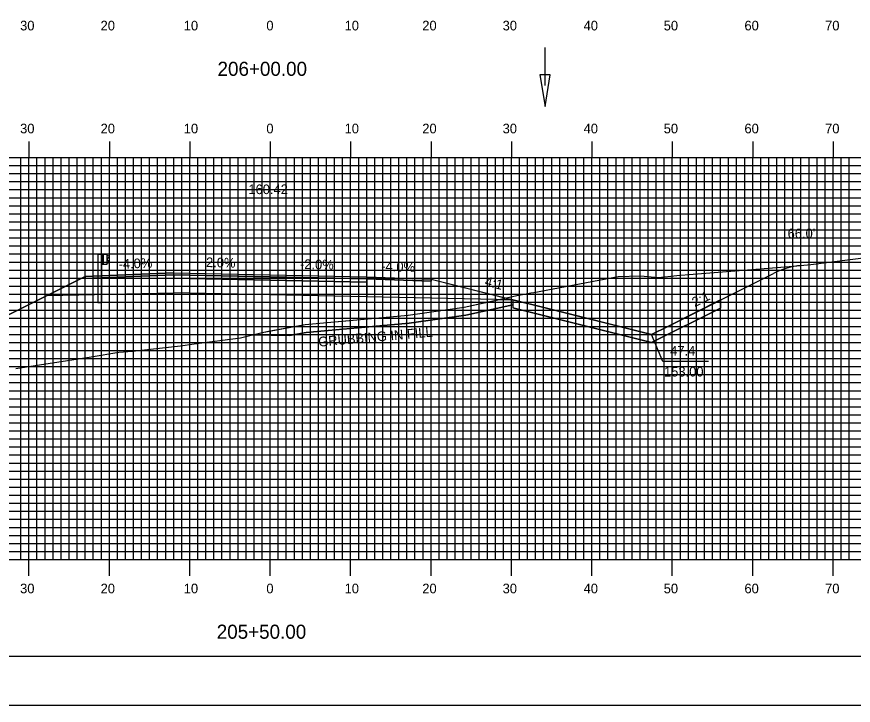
# Model space of a CAD drawing. Extents: x 1793272 to 1793615, y 442591 to 442811.
# Drawn here: x 1793406.3 to 1793510.3, y 442590.5 to 442676.2 of the extents above; entities that cross this region are included whole.
import ezdxf

# ---------------------------------------------------------------- set-up
doc = ezdxf.new("R2010")
doc.units = 0
for name, color, linetype in [('ANNOTATION', 7, 'Continuous'), ('BORDER', 7, 'Continuous'), ('D_Drainage_Ditch_Line', 7, 'Continuous'), ('D_Guardrail_Beam_Lt', 7, 'Continuous'), ('D_Roadway_Centerline', 7, 'Continuous'), ('D_Roadway_Centerline_Text', 7, 'Continuous'), ('D_Roadway_Edge_Shoulder', 7, 'Continuous'), ('D_Roadway_Edge_TW', 7, 'Continuous'), ('D_Roadway_FinishedGrade', 7, 'Continuous'), ('D_Roadway_Pavement', 7, 'Continuous'), ('D_Roadway_SlopeLines', 7, 'Continuous'), ('D_Roadway_SubGrade', 7, 'Continuous'), ('D_Text_Standard', 7, 'Continuous'), ('GRUBBING IN FILL', 7, 'Continuous'), ('H_V ANNOTATION', 7, 'Continuous'), ('MAJOR', 7, 'Continuous'), ('MINOR', 7, 'Continuous'), ('PATTERNING', 7, 'Continuous'), ('PLOT BOUNDARY', 7, 'Continuous'), ('S_Roadway_Centerline', 7, 'Continuous')]:
    doc.layers.add(name, color=color, linetype=linetype)

msp = doc.modelspace()

# ---------------------------------------------------------------- linework, layer by layer
at = {"layer": 'ANNOTATION'}
msp.add_lwpolyline([(1793492.31, 442633.3), (1793486.62, 442633.3), (1793485.23, 442636.67)], dxfattribs=at)
at = {"layer": 'BORDER'}
msp.add_lwpolyline([(1793288.2, 442596.67), (1793608.2, 442596.67), (1793608.2, 442806.67), (1793288.2, 442806.67)], close=True, dxfattribs=at)
at = {"layer": 'D_Drainage_Ditch_Line'}
msp.add_line((1793471.98, 442667.63), (1793471.97, 442672.33), dxfattribs=at)
msp.add_lwpolyline([(1793472.63, 442668.94), (1793471.32, 442668.94), (1793471.98, 442665)], close=True, dxfattribs=at)
at = {"layer": 'D_Guardrail_Beam_Lt'}
for p, q in [((1793416.37, 442646.59), (1793416.37, 442640.59)), ((1793416.84, 442646.59), (1793416.37, 442646.59)), ((1793417.53, 442646.59), (1793416.84, 442646.59)), ((1793416.84, 442646.59), (1793416.84, 442645.42)), ((1793416.9, 442646.59), (1793416.9, 442645.42)), ((1793417.01, 442646.59), (1793417.01, 442645.42)), ((1793417.53, 442645.42), (1793417.53, 442646.59)), ((1793417.53, 442646.5), (1793417.6, 442646.49)), ((1793417.53, 442646.04), (1793417.53, 442645.97)), ((1793417.76, 442646.24), (1793417.57, 442646.1)), ((1793417.57, 442645.9), (1793417.76, 442645.77)), ((1793417.62, 442646.48), (1793417.76, 442646.38)), ((1793416.84, 442645.42), (1793417.53, 442645.42)), ((1793416.86, 442640.59), (1793416.86, 442645.42)), ((1793417.6, 442645.52), (1793417.53, 442645.5)), ((1793417.76, 442645.62), (1793417.62, 442645.52)), ((1793416.86, 442640.59), (1793416.37, 442640.59))]:
    msp.add_line(p, q, dxfattribs=at)
for centre, major_axis, start_param, end_param in [((1793417.61, 442646.04), (-0.0789, 0), 5.323254, 6.283185), ((1793417.61, 442645.97), (-0.0789, 0), 6.283185, 7.243116), ((1793417.6, 442646.45), (0.0417, 0), 0.959931, 1.376053), ((1793417.71, 442646.31), (0.0877, 0), 5.323254, 7.243116), ((1793417.6, 442645.56), (0.0417, 0), 4.907132, 5.323254), ((1793417.71, 442645.7), (0.0877, 0), 5.323254, 7.243116)]:
    msp.add_ellipse(centre, major_axis=major_axis, ratio=0.995501, start_param=start_param, end_param=end_param, dxfattribs=at)
at = {"layer": 'D_Roadway_Centerline'}
msp.add_lwpolyline([(1793384.25, 442628.61), (1793410.05, 442641.51), (1793414.8, 442643.88), (1793417.8, 442644), (1793425.8, 442644.32), (1793437.8, 442644.08), (1793449.8, 442643.84), (1793457.8, 442643.52), (1793467.97, 442640.98), (1793471.97, 442639.98)], dxfattribs=at)
at = {"layer": 'D_Roadway_Edge_Shoulder'}
for points in [[(1793425.8, 442644.32), (1793417.8, 442644), (1793417.8, 442644), (1793414.8, 442643.88), (1793414.8, 442643.63), (1793425.8, 442644.07)], [(1793449.8, 442643.84), (1793457.8, 442643.52), (1793457.8, 442643.27), (1793449.8, 442643.59)]]:
    msp.add_lwpolyline(points, close=True, dxfattribs=at)
at = {"layer": 'D_Roadway_Edge_TW'}
msp.add_lwpolyline([(1793425.8, 442644.07), (1793425.8, 442644.32), (1793437.8, 442644.08), (1793449.8, 442643.84), (1793449.8, 442643.59), (1793437.8, 442643.83)], close=True, dxfattribs=at)
at = {"layer": 'D_Roadway_FinishedGrade'}
for p, q in [((1793457.8, 442643.52), (1793485.23, 442636.67)), ((1793467.97, 442640.98), (1793467.97, 442639.98))]:
    msp.add_line(p, q, dxfattribs=at)
for points in [[(1793485.23, 442636.67), (1793487.23, 442637.67), (1793500.39, 442644.25)], [(1793493.8, 442640.95), (1793493.8, 442639.95), (1793485.23, 442635.67)], [(1793485.23, 442635.67), (1793467.97, 442639.98)]]:
    msp.add_lwpolyline(points, dxfattribs=at)
msp.add_arc((1793504.86, 442635.3), 10, 96.007, 116.5651, dxfattribs=at)
at = {"layer": 'D_Roadway_Pavement'}
msp.add_lwpolyline([(1793425.8, 442643.66), (1793425.8, 442644.07), (1793437.8, 442643.83), (1793449.8, 442643.59), (1793449.8, 442643.18), (1793437.8, 442643.42)], close=True, dxfattribs=at)
for points in [[(1793425.8, 442644.07), (1793425.8, 442643.66)], [(1793449.8, 442643.59), (1793449.8, 442643.18)]]:
    msp.add_lwpolyline(points, dxfattribs=at)
at = {"layer": 'D_Roadway_SlopeLines'}
for points in [[(1793414.8, 442643.88), (1793384.25, 442628.61)], [(1793457.8, 442643.52), (1793471.97, 442639.98)]]:
    msp.add_lwpolyline(points, dxfattribs=at)
at = {"layer": 'D_Roadway_SubGrade'}
for points in [[(1793425.8, 442643.66), (1793425.8, 442644.07), (1793414.8, 442643.63), (1793414.8, 442643.88), (1793410.05, 442641.51), (1793425.8, 442641.82)], [(1793425.8, 442641.82), (1793425.8, 442644.07), (1793425.8, 442643.66), (1793437.8, 442643.42), (1793449.8, 442643.18), (1793449.8, 442643.59), (1793449.8, 442641.34), (1793437.8, 442641.58)], [(1793449.8, 442643.18), (1793449.8, 442643.59), (1793457.8, 442643.27), (1793457.8, 442643.52), (1793467.97, 442640.98), (1793449.8, 442641.34)]]:
    msp.add_lwpolyline(points, close=True, dxfattribs=at)
at = {"layer": 'GRUBBING IN FILL'}
for points in [[(1793437.8, 442636.58), (1793437.8, 442637.11), (1793442.15, 442637.91), (1793448.55, 442638.49), (1793454.95, 442639.07), (1793458.44, 442639.56), (1793461.93, 442640.04), (1793466.31, 442641.01), (1793467.97, 442640.98), (1793467.97, 442640.36), (1793462.11, 442639.06), (1793458.59, 442638.57), (1793455.07, 442638.08), (1793448.68, 442637.5), (1793442.28, 442636.92), (1793440.2, 442636.53)], [(1793437.8, 442636.58), (1793437.8, 442637.11), (1793442.15, 442637.91), (1793448.55, 442638.49), (1793454.95, 442639.07), (1793458.44, 442639.56), (1793461.93, 442640.04), (1793466.31, 442641.01), (1793467.97, 442640.98), (1793467.97, 442640.36), (1793462.11, 442639.06), (1793458.59, 442638.57), (1793455.07, 442638.08), (1793448.68, 442637.5), (1793442.28, 442636.92), (1793440.2, 442636.53)], [(1793435.62, 442636.63), (1793436.78, 442636.92), (1793437.8, 442637.11), (1793437.8, 442636.58)], [(1793435.62, 442636.63), (1793436.78, 442636.92), (1793437.8, 442637.11), (1793437.8, 442636.58)]]:
    msp.add_lwpolyline(points, close=True, dxfattribs=at)
for points in [[(1793440.2, 442636.53), (1793442.28, 442636.92), (1793455.07, 442638.08), (1793462.11, 442639.06), (1793467.97, 442640.36)], [(1793440.2, 442636.53), (1793442.28, 442636.92), (1793455.07, 442638.08), (1793462.11, 442639.06), (1793467.97, 442640.36)], [(1793435.62, 442636.63), (1793440.2, 442636.53)], [(1793435.62, 442636.63), (1793440.2, 442636.53)]]:
    msp.add_lwpolyline(points, dxfattribs=at)
at = {"layer": 'MAJOR'}
for p, q in [((1793407.8, 442660.67), (1793407.8, 442658.67)), ((1793417.8, 442660.67), (1793417.8, 442658.67)), ((1793427.8, 442660.67), (1793427.8, 442658.67)), ((1793437.8, 442660.67), (1793437.8, 442658.67)), ((1793447.8, 442660.67), (1793447.8, 442658.67)), ((1793457.8, 442660.67), (1793457.8, 442658.67)), ((1793467.8, 442660.67), (1793467.8, 442658.67)), ((1793477.8, 442660.67), (1793477.8, 442658.67)), ((1793487.8, 442660.67), (1793487.8, 442658.67)), ((1793497.8, 442660.67), (1793497.8, 442658.67)), ((1793507.8, 442660.67), (1793507.8, 442658.67)), ((1793297.8, 442658.67), (1793577.8, 442658.67)), ((1793297.8, 442658.67), (1793577.8, 442658.67)), ((1793407.8, 442608.67), (1793407.8, 442658.67)), ((1793417.8, 442608.67), (1793417.8, 442658.67)), ((1793427.8, 442608.67), (1793427.8, 442658.67)), ((1793437.8, 442608.67), (1793437.8, 442658.67)), ((1793447.8, 442608.67), (1793447.8, 442658.67)), ((1793457.8, 442608.67), (1793457.8, 442658.67)), ((1793467.8, 442608.67), (1793467.8, 442658.67)), ((1793477.8, 442608.67), (1793477.8, 442658.67)), ((1793487.8, 442608.67), (1793487.8, 442658.67)), ((1793497.8, 442608.67), (1793497.8, 442658.67)), ((1793507.8, 442608.67), (1793507.8, 442658.67)), ((1793297.8, 442653.67), (1793577.8, 442653.67)), ((1793297.8, 442648.67), (1793577.8, 442648.67)), ((1793297.8, 442643.67), (1793577.8, 442643.67)), ((1793297.8, 442638.67), (1793577.8, 442638.67)), ((1793297.8, 442633.67), (1793577.8, 442633.67)), ((1793297.8, 442628.67), (1793577.8, 442628.67)), ((1793297.8, 442623.67), (1793577.8, 442623.67)), ((1793297.8, 442618.67), (1793577.8, 442618.67)), ((1793297.8, 442613.67), (1793577.8, 442613.67)), ((1793297.8, 442608.67), (1793577.8, 442608.67)), ((1793297.8, 442608.67), (1793577.8, 442608.67)), ((1793407.8, 442606.66), (1793407.8, 442608.67)), ((1793417.8, 442606.66), (1793417.8, 442608.67)), ((1793427.8, 442606.66), (1793427.8, 442608.67)), ((1793437.8, 442606.66), (1793437.8, 442608.67)), ((1793447.8, 442606.66), (1793447.8, 442608.67)), ((1793457.8, 442606.66), (1793457.8, 442608.67)), ((1793467.8, 442606.66), (1793467.8, 442608.67)), ((1793477.8, 442606.66), (1793477.8, 442608.67)), ((1793487.8, 442606.66), (1793487.8, 442608.67)), ((1793497.8, 442606.66), (1793497.8, 442608.67)), ((1793507.8, 442606.66), (1793507.8, 442608.67))]:
    msp.add_line(p, q, dxfattribs=at)
at = {"layer": 'MINOR'}
for p, q in [((1793406.8, 442608.67), (1793406.8, 442658.67)), ((1793408.8, 442608.67), (1793408.8, 442658.67)), ((1793409.8, 442608.67), (1793409.8, 442658.67)), ((1793410.8, 442608.67), (1793410.8, 442658.67)), ((1793411.8, 442608.67), (1793411.8, 442658.67)), ((1793412.8, 442608.67), (1793412.8, 442658.67)), ((1793413.8, 442608.67), (1793413.8, 442658.67)), ((1793414.8, 442608.67), (1793414.8, 442658.67)), ((1793415.8, 442608.67), (1793415.8, 442658.67)), ((1793416.8, 442608.67), (1793416.8, 442658.67)), ((1793418.8, 442608.67), (1793418.8, 442658.67)), ((1793419.8, 442608.67), (1793419.8, 442658.67)), ((1793420.8, 442608.67), (1793420.8, 442658.67)), ((1793421.8, 442608.67), (1793421.8, 442658.67)), ((1793422.8, 442608.67), (1793422.8, 442658.67)), ((1793423.8, 442608.67), (1793423.8, 442658.67)), ((1793424.8, 442608.67), (1793424.8, 442658.67)), ((1793425.8, 442608.67), (1793425.8, 442658.67)), ((1793426.8, 442608.67), (1793426.8, 442658.67)), ((1793428.8, 442608.67), (1793428.8, 442658.67)), ((1793429.8, 442608.67), (1793429.8, 442658.67)), ((1793430.8, 442608.67), (1793430.8, 442658.67)), ((1793431.8, 442608.67), (1793431.8, 442658.67)), ((1793432.8, 442608.67), (1793432.8, 442658.67)), ((1793433.8, 442608.67), (1793433.8, 442658.67)), ((1793434.8, 442608.67), (1793434.8, 442658.67)), ((1793435.8, 442608.67), (1793435.8, 442658.67)), ((1793436.8, 442608.67), (1793436.8, 442658.67)), ((1793438.8, 442608.67), (1793438.8, 442658.67)), ((1793439.8, 442608.67), (1793439.8, 442658.67)), ((1793440.8, 442608.67), (1793440.8, 442658.67)), ((1793441.8, 442608.67), (1793441.8, 442658.67)), ((1793442.8, 442608.67), (1793442.8, 442658.67)), ((1793443.8, 442608.67), (1793443.8, 442658.67)), ((1793444.8, 442608.67), (1793444.8, 442658.67)), ((1793445.8, 442608.67), (1793445.8, 442658.67)), ((1793446.8, 442608.67), (1793446.8, 442658.67)), ((1793448.8, 442608.67), (1793448.8, 442658.67)), ((1793449.8, 442608.67), (1793449.8, 442658.67)), ((1793450.8, 442608.67), (1793450.8, 442658.67)), ((1793451.8, 442608.67), (1793451.8, 442658.67)), ((1793452.8, 442608.67), (1793452.8, 442658.67)), ((1793453.8, 442608.67), (1793453.8, 442658.67)), ((1793454.8, 442608.67), (1793454.8, 442658.67)), ((1793455.8, 442608.67), (1793455.8, 442658.67)), ((1793456.8, 442608.67), (1793456.8, 442658.67)), ((1793458.8, 442608.67), (1793458.8, 442658.67)), ((1793459.8, 442608.67), (1793459.8, 442658.67)), ((1793460.8, 442608.67), (1793460.8, 442658.67)), ((1793461.8, 442608.67), (1793461.8, 442658.67)), ((1793462.8, 442608.67), (1793462.8, 442658.67)), ((1793463.8, 442608.67), (1793463.8, 442658.67)), ((1793464.8, 442608.67), (1793464.8, 442658.67)), ((1793465.8, 442608.67), (1793465.8, 442658.67)), ((1793466.8, 442608.67), (1793466.8, 442658.67)), ((1793468.8, 442608.67), (1793468.8, 442658.67)), ((1793469.8, 442608.67), (1793469.8, 442658.67)), ((1793470.8, 442608.67), (1793470.8, 442658.67)), ((1793471.8, 442608.67), (1793471.8, 442658.67)), ((1793472.8, 442608.67), (1793472.8, 442658.67)), ((1793473.8, 442608.67), (1793473.8, 442658.67)), ((1793474.8, 442608.67), (1793474.8, 442658.67)), ((1793475.8, 442608.67), (1793475.8, 442658.67)), ((1793476.8, 442608.67), (1793476.8, 442658.67)), ((1793478.8, 442608.67), (1793478.8, 442658.67)), ((1793479.8, 442608.67), (1793479.8, 442658.67)), ((1793480.8, 442608.67), (1793480.8, 442658.67)), ((1793481.8, 442608.67), (1793481.8, 442658.67)), ((1793482.8, 442608.67), (1793482.8, 442658.67)), ((1793483.8, 442608.67), (1793483.8, 442658.67)), ((1793484.8, 442608.67), (1793484.8, 442658.67)), ((1793485.8, 442608.67), (1793485.8, 442658.67)), ((1793486.8, 442608.67), (1793486.8, 442658.67)), ((1793488.8, 442608.67), (1793488.8, 442658.67)), ((1793489.8, 442608.67), (1793489.8, 442658.67)), ((1793490.8, 442608.67), (1793490.8, 442658.67)), ((1793491.8, 442608.67), (1793491.8, 442658.67)), ((1793492.8, 442608.67), (1793492.8, 442658.67)), ((1793493.8, 442608.67), (1793493.8, 442658.67)), ((1793494.8, 442608.67), (1793494.8, 442658.67)), ((1793495.8, 442608.67), (1793495.8, 442658.67)), ((1793496.8, 442608.67), (1793496.8, 442658.67)), ((1793498.8, 442608.67), (1793498.8, 442658.67)), ((1793499.8, 442608.67), (1793499.8, 442658.67)), ((1793500.8, 442608.67), (1793500.8, 442658.67)), ((1793501.8, 442608.67), (1793501.8, 442658.67)), ((1793502.8, 442608.67), (1793502.8, 442658.67)), ((1793503.8, 442608.67), (1793503.8, 442658.67)), ((1793504.8, 442608.67), (1793504.8, 442658.67)), ((1793505.8, 442608.67), (1793505.8, 442658.67)), ((1793506.8, 442608.67), (1793506.8, 442658.67)), ((1793508.8, 442608.67), (1793508.8, 442658.67)), ((1793509.8, 442608.67), (1793509.8, 442658.67)), ((1793297.8, 442657.67), (1793577.8, 442657.67)), ((1793297.8, 442656.67), (1793577.8, 442656.67)), ((1793297.8, 442655.67), (1793577.8, 442655.67)), ((1793297.8, 442654.67), (1793577.8, 442654.67)), ((1793297.8, 442652.67), (1793577.8, 442652.67)), ((1793297.8, 442651.67), (1793577.8, 442651.67)), ((1793297.8, 442650.67), (1793577.8, 442650.67)), ((1793297.8, 442649.67), (1793577.8, 442649.67)), ((1793297.8, 442647.67), (1793577.8, 442647.67)), ((1793297.8, 442646.67), (1793577.8, 442646.67)), ((1793297.8, 442645.67), (1793577.8, 442645.67)), ((1793297.8, 442644.67), (1793577.8, 442644.67)), ((1793297.8, 442642.67), (1793577.8, 442642.67)), ((1793297.8, 442641.67), (1793577.8, 442641.67)), ((1793297.8, 442640.67), (1793577.8, 442640.67)), ((1793297.8, 442639.67), (1793577.8, 442639.67)), ((1793297.8, 442637.67), (1793577.8, 442637.67)), ((1793297.8, 442636.67), (1793577.8, 442636.67)), ((1793297.8, 442635.67), (1793577.8, 442635.67)), ((1793297.8, 442634.67), (1793577.8, 442634.67)), ((1793297.8, 442632.67), (1793577.8, 442632.67)), ((1793297.8, 442631.67), (1793577.8, 442631.67)), ((1793297.8, 442630.67), (1793577.8, 442630.67)), ((1793297.8, 442629.67), (1793577.8, 442629.67)), ((1793297.8, 442627.67), (1793577.8, 442627.67)), ((1793297.8, 442626.67), (1793577.8, 442626.67)), ((1793297.8, 442625.67), (1793577.8, 442625.67)), ((1793297.8, 442624.67), (1793577.8, 442624.67)), ((1793297.8, 442622.67), (1793577.8, 442622.67)), ((1793297.8, 442621.67), (1793577.8, 442621.67)), ((1793297.8, 442620.67), (1793577.8, 442620.67)), ((1793297.8, 442619.67), (1793577.8, 442619.67)), ((1793297.8, 442617.67), (1793577.8, 442617.67)), ((1793297.8, 442616.67), (1793577.8, 442616.67)), ((1793297.8, 442615.67), (1793577.8, 442615.67)), ((1793297.8, 442614.67), (1793577.8, 442614.67)), ((1793297.8, 442612.67), (1793577.8, 442612.67)), ((1793297.8, 442611.67), (1793577.8, 442611.67)), ((1793297.8, 442610.67), (1793577.8, 442610.67)), ((1793297.8, 442609.67), (1793577.8, 442609.67))]:
    msp.add_line(p, q, dxfattribs=at)
at = {"layer": 'PATTERNING'}
for p, q in [((1793471.97, 442639.98), (1793467.97, 442640.98)), ((1793467.97, 442640.98), (1793467.97, 442639.98)), ((1793493.8, 442640.95), (1793487.23, 442637.67)), ((1793467.97, 442639.98), (1793485.23, 442635.67)), ((1793485.23, 442636.67), (1793471.97, 442639.98)), ((1793487.23, 442637.67), (1793485.23, 442636.67))]:
    msp.add_line(p, q, dxfattribs=at)
msp.add_lwpolyline([(1793485.23, 442635.67), (1793493.8, 442639.95), (1793493.8, 442640.95)], dxfattribs=at)
at = {"layer": 'PLOT BOUNDARY'}
msp.add_lwpolyline([(1793272.01, 442590.55), (1793612.01, 442590.55), (1793612.01, 442810.55), (1793272.01, 442810.55)], close=True, dxfattribs=at)
at = {"layer": 'S_Roadway_Centerline'}
msp.add_lwpolyline([(1793406.17, 442632.44), (1793415.52, 442633.88), (1793418.98, 442634.45), (1793420.69, 442634.6), (1793426.65, 442635.24), (1793428.35, 442635.5), (1793434.09, 442636.24), (1793436.78, 442636.92), (1793442.15, 442637.91), (1793454.95, 442639.07), (1793461.93, 442640.04), (1793468.67, 442641.53), (1793469.42, 442641.67), (1793470.22, 442641.84), (1793470.6, 442641.89), (1793481.05, 442643.88), (1793483.85, 442643.93), (1793486.1, 442643.75), (1793488.35, 442643.99), (1793490.39, 442644.17), (1793502.85, 442645.14), (1793505.02, 442645.37), (1793517.09, 442646.88)], dxfattribs=at)

# ---------------------------------------------------------------- texts
at = {"layer": 'ANNOTATION'}
for s, rotation, p in [('-4.0%', 2.2906, (1793418.97, 442644.81)), ('2.0%', 358.8542, (1793429.81, 442645.04)), ('-2.0%', 358.8542, (1793441.49, 442644.81)), ('-4.0%', 357.7094, (1793451.59, 442644.57)), ('4:1', 345.9638, (1793464.39, 442642.74)), ('2:1', 26.5651, (1793490.61, 442640.04))]:
    msp.add_text(s, height=1.2, rotation=rotation, dxfattribs=at).set_placement(p)
for s, p in [("47.4'", (1793487.53, 442634.03)), ('153.00', (1793486.77, 442631.43))]:
    msp.add_text(s, height=1.2, dxfattribs=at).set_placement(p)
at = {"layer": 'D_Roadway_Centerline'}
for s in ['C', 'L']:
    msp.add_text(s, height=0.0146, dxfattribs=at).set_placement((1793437.8, 442644.08))
at = {"layer": 'D_Roadway_Centerline_Text'}
msp.add_text('160.42', height=1.2, dxfattribs=at).set_placement((1793435.09, 442654.11))
at = {"layer": 'D_Text_Standard'}
msp.add_text("66.0'", height=1.2, dxfattribs=at).set_placement((1793502.14, 442648.62))
at = {"layer": 'GRUBBING IN FILL'}
msp.add_text('GRUBBING IN FILL', height=1.2, rotation=5.0472, dxfattribs=at).set_placement((1793443.83, 442635.14))
at = {"layer": 'H_V ANNOTATION'}
for s, height, p in [('30', 1.2, (1793406.7, 442674.47)), ('20', 1.2, (1793416.71, 442674.47)), ('10', 1.2, (1793427.05, 442674.47)), ('0', 1.2, (1793437.32, 442674.47)), ('10', 1.2, (1793447.05, 442674.47)), ('20', 1.2, (1793456.71, 442674.47)), ('30', 1.2, (1793466.7, 442674.47)), ('40', 1.2, (1793476.77, 442674.47)), ('50', 1.2, (1793486.73, 442674.47)), ('60', 1.2, (1793496.77, 442674.47)), ('70', 1.2, (1793506.8, 442674.47)), ('206+00.00', 1.75, (1793431.25, 442668.82)), ('30', 1.2, (1793406.7, 442661.67)), ('20', 1.2, (1793416.71, 442661.67)), ('10', 1.2, (1793427.05, 442661.67)), ('0', 1.2, (1793437.32, 442661.67)), ('10', 1.2, (1793447.05, 442661.67)), ('20', 1.2, (1793456.71, 442661.67)), ('30', 1.2, (1793466.7, 442661.67)), ('40', 1.2, (1793476.77, 442661.67)), ('50', 1.2, (1793486.73, 442661.67)), ('60', 1.2, (1793496.77, 442661.67)), ('70', 1.2, (1793506.8, 442661.67)), ('30', 1.2, (1793406.7, 442604.47)), ('20', 1.2, (1793416.71, 442604.47)), ('10', 1.2, (1793427.05, 442604.47)), ('0', 1.2, (1793437.32, 442604.47)), ('10', 1.2, (1793447.05, 442604.47)), ('20', 1.2, (1793456.71, 442604.47)), ('30', 1.2, (1793466.7, 442604.47)), ('40', 1.2, (1793476.77, 442604.47)), ('50', 1.2, (1793486.73, 442604.47)), ('60', 1.2, (1793496.77, 442604.47)), ('70', 1.2, (1793506.8, 442604.47)), ('205+50.00', 1.75, (1793431.15, 442598.82))]:
    msp.add_text(s, height=height, dxfattribs=at).set_placement(p)

doc.saveas('drawing.dxf')
